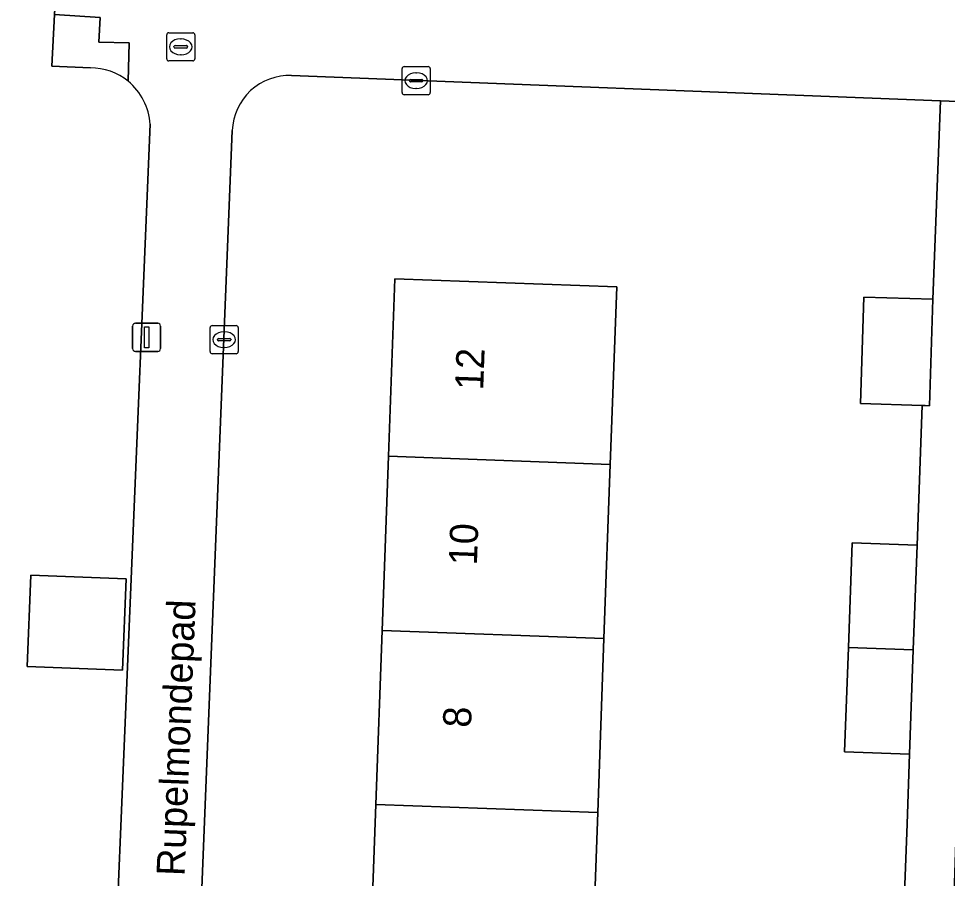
# Model space of a CAD drawing. Extents: x 160732 to 162107, y 387428 to 388479.
# Drawn here: x 161157.41 to 161190.39, y 387641.26 to 387671.79 of the extents above; entities that cross this region are included whole.
import ezdxf

# ---------------------------------------------------------------- set-up
doc = ezdxf.new("R2010")
doc.units = 0
for name, color, linetype in [('IMGEO_Erf', 7, 'Continuous'), ('IMGEO_Groenvoorziening', 7, 'Continuous'), ('IMGEO_Kolk', 7, 'Continuous'), ('IMGEO_Lichtmast', 7, 'Continuous'), ('IMGEO_Openbare_ruimte_label', 7, 'Continuous'), ('IMGEO_Pand', 7, 'Continuous'), ('IMGEO_Pand_nummerreeks', 7, 'Continuous'), ('IMGEO_Rioolput', 7, 'Continuous'), ('IMGEO_Voetpad_open', 7, 'Continuous')]:
    doc.layers.add(name, color=color, linetype=linetype)

msp = doc.modelspace()

# ---------------------------------------------------------------- linework, layer by layer
at = {"layer": 'IMGEO_Erf'}
for points in [[(161159.959, 387670.036), (161158.584, 387670.098), (161158.688, 387671.93), (161159.084, 387678.892), (161158.458, 387679.941), (161157.536, 387680.714), (161152.408, 387680.842), (161152.037, 387671.309), (161153.057, 387671.269), (161152.809, 387664.891), (161153.788, 387664.853), (161153.54, 387658.474), (161153.292, 387652.096), (161153.046, 387645.765), (161150.218, 387645.875), (161150.216, 387645.828), (161152.873, 387645.725), (161152.625, 387639.347), (161149.968, 387639.45), (161149.72, 387633.072), (161149.469, 387626.618), (161158.888, 387626.423)], [(161186.869, 387649.461), (161187.003, 387653.172), (161189.309, 387653.088), (161189.489, 387658.05), (161187.301, 387658.116), (161187.416, 387661.896), (161189.863, 387661.822), (161190.137, 387668.865), (161167.1, 387669.761)], [(161160.402, 387628.151), (161160.634, 387633.476), (161162.076, 387668.034)], [(161164.993, 387667.816), (161163.591, 387632.934), (161163.389, 387627.589)], [(161169.864, 387637.697), (161170.088, 387643.88), (161170.312, 387650.062), (161170.536, 387656.245), (161170.765, 387662.548), (161178.645, 387662.262), (161178.416, 387655.959), (161178.192, 387649.776), (161177.968, 387643.594), (161177.744, 387637.411)], [(161188.861, 387640.723), (161188.951, 387643.195), (161189.041, 387645.666), (161186.735, 387645.75), (161186.869, 387649.461)]]:
    msp.add_lwpolyline(points, dxfattribs=at)
msp.add_lwpolyline([(161157.839, 387652.027), (161161.221, 387651.895), (161161.095, 387648.656), (161157.713, 387648.787)], close=True, dxfattribs=at)
for centre, radius, start, end in [((161159.96, 387667.912), 2.124, 50.9717, 90.0139), ((161167.016, 387667.738), 2.025, 87.6228, 177.7983), ((161159.946, 387667.91), 2.134, 3.3192, 50.7073)]:
    msp.add_arc(centre, radius, start, end, dxfattribs=at)
at = {"layer": 'IMGEO_Groenvoorziening'}
for points in [[(161161.33, 387670.927), (161160.256, 387670.943), (161160.3, 387671.821), (161158.688, 387671.93), (161158.584, 387670.098), (161159.959, 387670.036)], [(161161.297, 387669.562), (161161.33, 387670.927)]]:
    msp.add_lwpolyline(points, dxfattribs=at)
msp.add_arc((161159.96, 387667.912), 2.124, 50.9717, 90.0139, dxfattribs=at)
at = {"layer": 'IMGEO_Kolk'}
for p, q in [((161171.098, 387670.081), (161171.95, 387670.081)), ((161171.023, 387669.155), (161171.023, 387670.007)), ((161171.511, 387669.861), (161171.536, 387669.861)), ((161172.024, 387670.007), (161172.024, 387669.155)), ((161171.282, 387669.575), (161171.282, 387669.587)), ((161171.72, 387669.538), (161171.322, 387669.538)), ((161171.325, 387669.624), (161171.723, 387669.624)), ((161171.766, 387669.587), (161171.766, 387669.575)), ((161171.95, 387669.081), (161171.098, 387669.081)), ((161171.534, 387669.301), (161171.509, 387669.301)), ((161164.206, 387659.96), (161164.206, 387660.812)), ((161164.281, 387660.886), (161165.133, 387660.886)), ((161165.207, 387660.812), (161165.207, 387659.96)), ((161164.694, 387660.666), (161164.719, 387660.666)), ((161164.465, 387660.38), (161164.465, 387660.392)), ((161164.903, 387660.343), (161164.505, 387660.343)), ((161164.508, 387660.429), (161164.906, 387660.429)), ((161164.949, 387660.392), (161164.949, 387660.38)), ((161165.133, 387659.886), (161164.281, 387659.886)), ((161164.717, 387660.106), (161164.692, 387660.106))]:
    msp.add_line(p, q, dxfattribs=at)
for points in [[(161171.098, 387670.081), (161171.95, 387670.081)], [(161171.023, 387669.155), (161171.023, 387670.007)], [(161172.024, 387670.007), (161172.024, 387669.155)], [(161171.95, 387669.081), (161171.098, 387669.081)], [(161164.206, 387659.96), (161164.206, 387660.812)], [(161164.281, 387660.886), (161165.133, 387660.886)], [(161165.207, 387660.812), (161165.207, 387659.96)], [(161165.133, 387659.886), (161164.281, 387659.886)]]:
    msp.add_lwpolyline(points, dxfattribs=at)
for centre, radius, start, end in [((161171.1, 387670.005), 0.0765, 91.552, 178.448), ((161171.1, 387670.005), 0.0765, 91.552, 178.448), ((161171.948, 387670.005), 0.0765, 1.552, 88.448), ((161171.948, 387670.005), 0.0765, 1.552, 88.448), ((161171.322, 387669.584), 0.0403, 85.8775, 175.7526), ((161171.319, 387669.574), 0.0366, 178.938, 274.7102), ((161171.723, 387669.581), 0.043, 264.8664, 352.4533), ((161171.727, 387669.586), 0.0386, 1.7309, 96.639), ((161171.1, 387669.157), 0.0765, 181.552, 268.448), ((161171.1, 387669.157), 0.0765, 181.552, 268.448), ((161171.948, 387669.157), 0.0765, 271.552, 358.448), ((161171.948, 387669.157), 0.0765, 271.552, 358.448), ((161164.283, 387660.81), 0.0765, 91.552, 178.448), ((161164.283, 387660.81), 0.0765, 91.552, 178.448), ((161165.131, 387660.81), 0.0765, 1.552, 88.448), ((161165.131, 387660.81), 0.0765, 1.552, 88.448), ((161164.505, 387660.389), 0.0403, 85.8775, 175.7526), ((161164.502, 387660.379), 0.0366, 178.938, 274.7102), ((161164.906, 387660.386), 0.043, 264.8664, 352.4533), ((161164.91, 387660.391), 0.0386, 1.7309, 96.639), ((161164.283, 387659.962), 0.0765, 181.552, 268.448), ((161164.283, 387659.962), 0.0765, 181.552, 268.448), ((161165.131, 387659.962), 0.0765, 271.552, 358.448), ((161165.131, 387659.962), 0.0765, 271.552, 358.448)]:
    msp.add_arc(centre, radius, start, end, dxfattribs=at)
for centre, major_axis, ratio, start_param, end_param in [((161171.51, 387669.581), (-0.387, 0.002), 0.722429, 4.712389, 7.853982), ((161171.535, 387669.581), (-0.39, 0.002), 0.717154, 1.570796, 4.712389), ((161164.693, 387660.386), (-0.387, 0.002), 0.722429, 4.712389, 7.853982), ((161164.718, 387660.386), (-0.39, 0.002), 0.717154, 1.570796, 4.712389)]:
    msp.add_ellipse(centre, major_axis=major_axis, ratio=ratio, start_param=start_param, end_param=end_param, dxfattribs=at)
at = {"layer": 'IMGEO_Lichtmast'}
for p, q in [((161161.457, 387660.068), (161161.457, 387660.868)), ((161161.457, 387660.868), (161161.457, 387660.068)), ((161161.557, 387660.968), (161162.347, 387660.968)), ((161162.347, 387660.968), (161161.557, 387660.968)), ((161162.447, 387660.868), (161162.447, 387660.068)), ((161162.447, 387660.068), (161162.447, 387660.868)), ((161162.347, 387659.968), (161161.557, 387659.968)), ((161161.557, 387659.968), (161162.347, 387659.968))]:
    msp.add_line(p, q, dxfattribs=at)
msp.add_lwpolyline([(161161.877, 387660.843), (161162.027, 387660.843), (161162.027, 387660.093), (161161.877, 387660.093), (161161.877, 387660.843)], dxfattribs=at)
for centre, start, end in [((161161.557, 387660.868), 90, 180), ((161161.557, 387660.868), 90, 180), ((161162.347, 387660.868), 0, 90), ((161162.347, 387660.868), 360, 90), ((161161.557, 387660.068), 180, 270), ((161161.557, 387660.068), 180, 270), ((161162.347, 387660.068), 270, 0), ((161162.347, 387660.068), 270, 0)]:
    msp.add_arc(centre, 0.1, start, end, dxfattribs=at)
at = {"layer": 'IMGEO_Pand'}
for points in [[(161178.416, 387655.959), (161178.645, 387662.262), (161170.765, 387662.548), (161170.536, 387656.245)], [(161189.863, 387661.822), (161187.416, 387661.896), (161187.301, 387658.116), (161189.489, 387658.05), (161189.591, 387658.047), (161189.749, 387658.042)], [(161178.192, 387649.776), (161178.416, 387655.959), (161170.536, 387656.245), (161170.312, 387650.062)], [(161189.309, 387653.088), (161187.003, 387653.172), (161186.869, 387649.461), (161189.175, 387649.377)], [(161161.221, 387651.895), (161157.839, 387652.027), (161157.713, 387648.787), (161161.095, 387648.656)], [(161170.312, 387650.062), (161170.088, 387643.88), (161177.968, 387643.594), (161178.192, 387649.776)], [(161189.175, 387649.377), (161186.869, 387649.461), (161186.735, 387645.75), (161189.041, 387645.666)], [(161177.744, 387637.411), (161177.968, 387643.594), (161170.088, 387643.88), (161169.864, 387637.697)]]:
    msp.add_lwpolyline(points, close=True, dxfattribs=at)
at = {"layer": 'IMGEO_Rioolput'}
for p, q in [((161162.665, 387670.356), (161162.665, 387671.208)), ((161162.74, 387671.282), (161163.592, 387671.282)), ((161163.153, 387671.062), (161163.178, 387671.062)), ((161163.666, 387671.208), (161163.666, 387670.356)), ((161162.924, 387670.776), (161162.924, 387670.788)), ((161163.362, 387670.739), (161162.964, 387670.739)), ((161162.967, 387670.825), (161163.365, 387670.825)), ((161163.408, 387670.788), (161163.408, 387670.776)), ((161163.176, 387670.502), (161163.151, 387670.502)), ((161163.592, 387670.282), (161162.74, 387670.282))]:
    msp.add_line(p, q, dxfattribs=at)
for points in [[(161162.665, 387670.356), (161162.665, 387671.208)], [(161162.74, 387671.282), (161163.592, 387671.282)], [(161163.666, 387671.208), (161163.666, 387670.356)], [(161163.592, 387670.282), (161162.74, 387670.282)]]:
    msp.add_lwpolyline(points, dxfattribs=at)
for centre, radius, start, end in [((161162.742, 387671.206), 0.0765, 91.552, 178.448), ((161162.742, 387671.206), 0.0765, 91.552, 178.448), ((161163.59, 387671.206), 0.0765, 1.552, 88.448), ((161163.59, 387671.206), 0.0765, 1.552, 88.448), ((161162.964, 387670.785), 0.0403, 85.8775, 175.7526), ((161162.961, 387670.775), 0.0366, 178.938, 274.7102), ((161163.365, 387670.782), 0.043, 264.8664, 352.4533), ((161163.369, 387670.787), 0.0386, 1.7309, 96.639), ((161162.742, 387670.358), 0.0765, 181.552, 268.448), ((161162.742, 387670.358), 0.0765, 181.552, 268.448), ((161163.59, 387670.358), 0.0765, 271.552, 358.448), ((161163.59, 387670.358), 0.0765, 271.552, 358.448)]:
    msp.add_arc(centre, radius, start, end, dxfattribs=at)
for centre, major_axis, ratio, start_param, end_param in [((161163.152, 387670.782), (-0.387, 0.002), 0.722429, 4.712389, 7.853982), ((161163.177, 387670.782), (-0.39, 0.002), 0.717154, 1.570796, 4.712389)]:
    msp.add_ellipse(centre, major_axis=major_axis, ratio=ratio, start_param=start_param, end_param=end_param, dxfattribs=at)
at = {"layer": 'IMGEO_Voetpad_open'}
for points in [[(161124.277, 387681.994), (161126.614, 387681.9), (161132.542, 387681.663), (161140.997, 387681.285), (161152.408, 387680.842), (161157.536, 387680.714), (161158.458, 387679.941), (161159.084, 387678.892), (161158.688, 387671.93), (161160.3, 387671.821), (161160.256, 387670.943), (161161.33, 387670.927), (161161.297, 387669.562)], [(161167.1, 387669.761), (161190.137, 387668.865), (161191.672, 387668.805), (161229.173, 387667.346), (161230.667, 387667.288), (161250.028, 387666.535), (161255.329, 387666.321)], [(161162.076, 387668.034), (161160.634, 387633.476), (161160.402, 387628.151)], [(161163.389, 387627.589), (161163.591, 387632.934), (161164.993, 387667.816)]]:
    msp.add_lwpolyline(points, dxfattribs=at)
msp.add_lwpolyline([(161190.916, 387649.969), (161191.08, 387653.992), (161191.193, 387656.764), (161191.398, 387661.759), (161191.672, 387668.805), (161190.137, 387668.865), (161189.863, 387661.822), (161189.749, 387658.042), (161189.591, 387658.047), (161189.489, 387658.05), (161189.309, 387653.088), (161189.175, 387649.377), (161189.041, 387645.666), (161188.951, 387643.195), (161188.861, 387640.723), (161188.727, 387637.012), (161188.593, 387633.302), (161188.489, 387630.449), (161190.239, 387630.36), (161190.532, 387637.753)], close=True, dxfattribs=at)
for centre, radius, start, end in [((161167.016, 387667.738), 2.025, 87.6228, 177.7983), ((161159.946, 387667.91), 2.134, 3.3192, 50.7073)]:
    msp.add_arc(centre, radius, start, end, dxfattribs=at)

# ---------------------------------------------------------------- texts
at = {"layer": 'IMGEO_Openbare_ruimte_label'}
msp.add_text('Rupelmondepad', height=1, rotation=87.7071, dxfattribs=at).set_placement((161163.301, 387641.331))
at = {"layer": 'IMGEO_Pand_nummerreeks'}
for s, p in [('12', (161173.903, 387658.58)), ('10', (161173.679, 387652.363)), ('8', (161173.469, 387646.6))]:
    msp.add_text(s, height=1, rotation=87.9232, dxfattribs=at).set_placement(p)

doc.saveas('drawing.dxf')
